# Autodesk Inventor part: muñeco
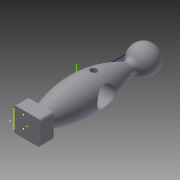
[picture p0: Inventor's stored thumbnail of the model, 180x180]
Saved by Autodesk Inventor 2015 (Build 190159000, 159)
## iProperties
Created: 2016-05
Part Number: muñeco
Material: Genérico
Document SubType Name: Modeling
Designer: ALEX
Density: 1 g/cm^3
Appearance: Valor por defecto
Author: ALEX
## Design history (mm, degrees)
sketch "Boceto1"
  geometry: L1 (0, 0)-(0, 100.375); L2 (0, 88.193)-(0, 73.709); L3 (-6, 12.866)-(0, 12.866); A1 r 10 centre (0, 90.375) between (0, 100.375) and (-5.979, 82.359); A2 r 78 centre (65.821, 43.292) between (-4.606, 76.818) and (-6, 12.866); A3 r 4.5 centre (-8.669, 78.752) between (-4.606, 76.818) and (-5.979, 82.359)
  constraints: 6 end point, 6 point on circle, 3 centre point, 3 point on line, 2 tangent, 1 horizontal, 1 vertical
  dimensions: "d1" = 78 radius of A2; "d2" = 10 radius of A1; "d3" = 6 distance of L3.start L3.end; "d4" = 9 diameter of A3
revolve "Revolución1" sketch "Boceto1" stored, may be unused: angle "d5" = 90 deg
sketch "Boceto2"
  geometry: L1 (10, 9.091)-(-10, 9.091); L2 (-10, 9.091)-(-10, -9.091); L3 (-10, -9.091)-(10, -9.091); L4 (10, -9.091)-(10, 9.091); L5 (10, 9.091)-(-10, -9.091); L6 (-10, 9.091)-(10, -9.091); 1 further point
  constraints: 12 end point, 2 midpoint, 2 parallel, 1 horizontal, 1 perpendicular
  dimensions: "d6" = 20 distance of L3.end L2.end
extrude "Extrusión1" join sketch "Boceto2" distance "d7" = 10; taper "d8" = 0 deg
fillet "Empalme1" dims "d9" = 2
fillet "Empalme2" dims "d10" = 2
fillet "Empalme3" dims "d11" = 2
fillet "Empalme4" dims "d12" = 2
sketch "Boceto3"
  geometry: 1 further point
fillet "Empalme5" dims "d13" = 2
sketch "Boceto4"
  geometry: 1 further point
node "Plano de trabajo1"
sketch "Boceto5"
  geometry: C1 r 7.5 at (-39.281, 0); 1 further point
  constraints: 1 centre point
  dimensions: "d14" = 15 diameter of C1
extrude "Extrusión2" cut sketch "Boceto5" stored distance "d15" = 50; taper "d16" = 0 deg
node "Plano de trabajo2"
sketch "Boceto6"
  geometry: C1 r 2.5 at (0, 52.814); 1 further point
  constraints: 1 centre point
  dimensions: "d17" = 5 diameter of C1
extrude "Extrusión3" cut sketch "Boceto6" stored distance "d18" = 50; taper "d19" = 0 deg
sketch "Boceto7"
  geometry: 1 further point
sketch "Boceto8"
  geometry: L1 (-14.182, 0)-(0, 0) reference; L2 (-7.091, 0)-(-7.091, 87.509); L3 (-18.38, 47.013)-(5.02, 47.013); 1 further point
  constraints: 4 end point, 1 horizontal, 1 midpoint, 1 vertical
node "Sólido1"
